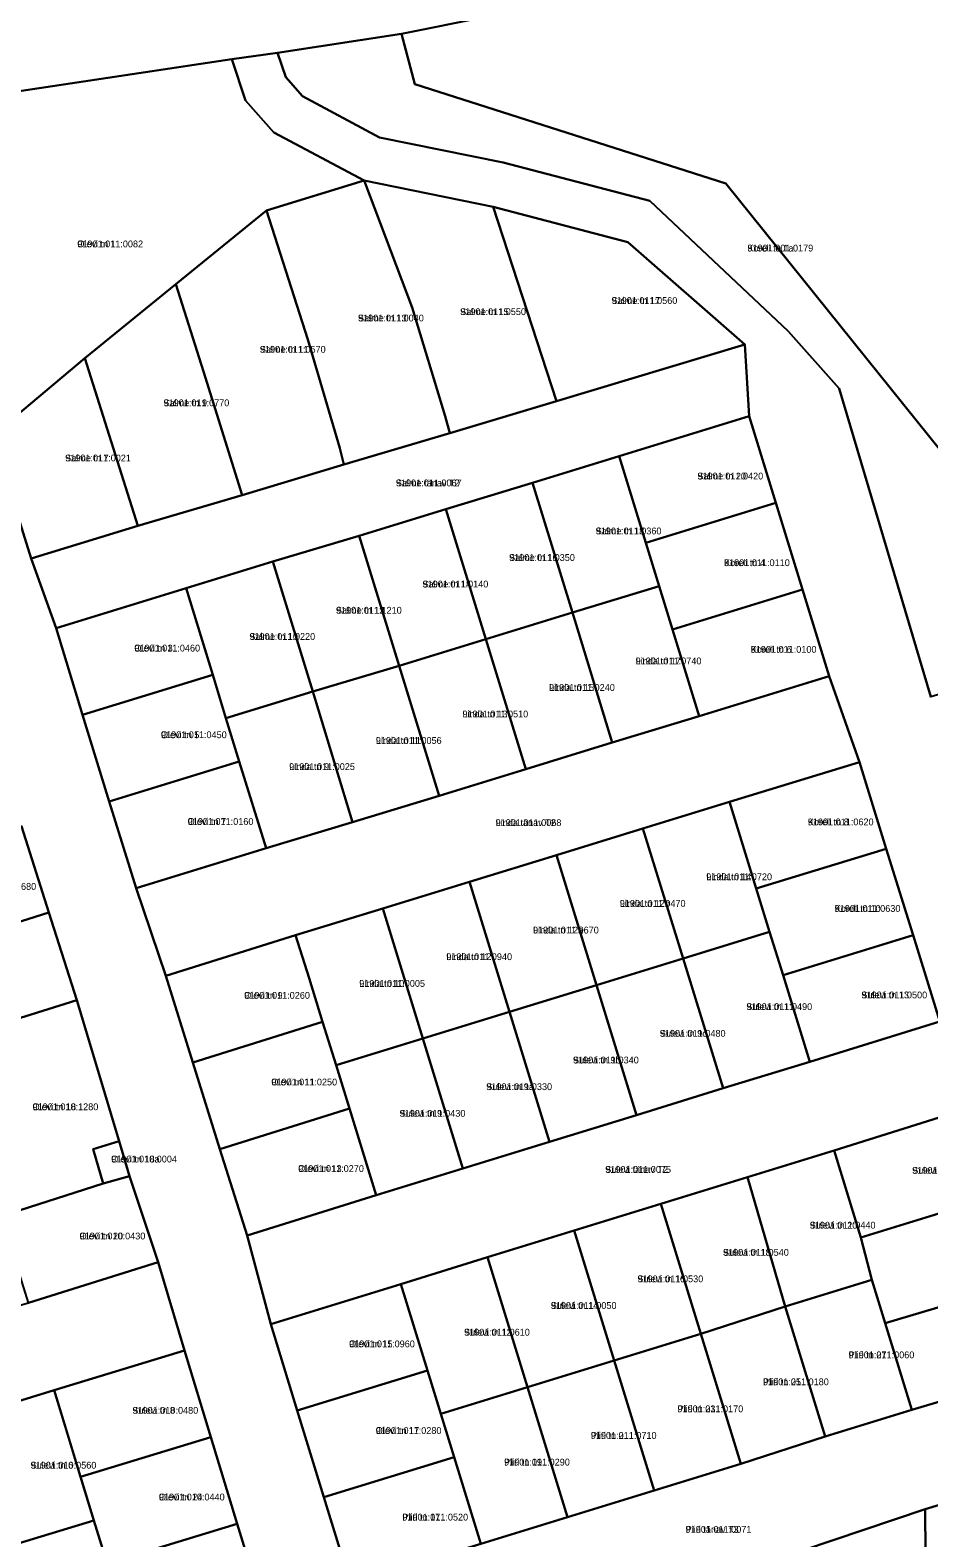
# Model space of a CAD drawing. Extents: x 675810 to 681273, y 6411190 to 6417565.
# Drawn here: x 678729.6 to 678927.8, y 6414897.2 to 6415229.9 of the extents above; entities that cross this region are included whole.
import ezdxf

# ---------------------------------------------------------------- set-up
doc = ezdxf.new("R2010")
doc.units = 0
for name, color, linetype in [('L_AADRESS', 7, 'Continuous'), ('PIIR', 7, 'Continuous'), ('TUNNUS', 7, 'Continuous')]:
    doc.layers.add(name, color=color, linetype=linetype)

msp = doc.modelspace()

# ---------------------------------------------------------------- linework, layer by layer
at = {"layer": 'PIIR'}
for points in [[(678938.21, 6415256.44), (678940.28, 6415250.38), (678947.08, 6415252.89), (678953.18, 6415237.02), (678971.88, 6415192.56), (678991.54, 6415146.92), (678991.43, 6415107.45), (678951.01, 6415123.4), (678930.74, 6415136.65), (678883.06, 6415196.06), (678814.45, 6415217.97), (678811.5, 6415229.05), (678924.62, 6415251.82)], [(678811.5, 6415229.05), (678814.45, 6415217.97), (678883.06, 6415196.06), (678930.74, 6415136.65), (678951.01, 6415123.4), (678991.43, 6415107.45), (678976.51, 6415097.38), (678928.23, 6415082.74), (678907.99, 6415150.83), (678896.81, 6415163.44), (678866.24, 6415192.19), (678833.97, 6415200.67), (678806.69, 6415206.19), (678789.69, 6415215.27), (678785.99, 6415219.46), (678784.18, 6415224.88)], [(678698.84, 6415212.11), (678774.11, 6415223.46), (678777.15, 6415214.36), (678783.39, 6415207.3), (678803.29, 6415196.66), (678781.73, 6415190.06), (678761.76, 6415173.8), (678741.72, 6415157.52), (678721.36, 6415140.44)], [(678822.16, 6415140.93), (678798.84, 6415134.04), (678797.92, 6415137.65), (678790.9, 6415161.63), (678781.73, 6415190.06), (678803.29, 6415196.66), (678813.86, 6415168.64), (678821.16, 6415144.73)], [(678821.16, 6415144.73), (678813.86, 6415168.64), (678803.29, 6415196.66), (678831.73, 6415190.9), (678845.66, 6415148.02), (678822.16, 6415140.93)], [(678861.44, 6415183.09), (678887.2, 6415160.51), (678845.66, 6415148.02), (678831.73, 6415190.9)], [(678781.73, 6415190.06), (678790.9, 6415161.63), (678797.92, 6415137.65), (678798.84, 6415134.04), (678776.38, 6415127.3), (678767.84, 6415154.55), (678761.76, 6415173.8)], [(678741.72, 6415157.52), (678761.76, 6415173.8), (678767.84, 6415154.55), (678776.38, 6415127.3), (678753.36, 6415120.49)], [(678721.36, 6415140.44), (678741.72, 6415157.52), (678753.36, 6415120.49), (678729.87, 6415113.29)], [(678729.87, 6415113.29), (678753.36, 6415120.49), (678776.38, 6415127.3), (678798.84, 6415134.04), (678822.16, 6415140.93), (678845.66, 6415148.02), (678887.2, 6415160.51), (678888.18, 6415144.69), (678859.5, 6415135.89), (678840.39, 6415130.02), (678821.32, 6415124.18), (678802.2, 6415118.31), (678783.14, 6415112.61), (678764.02, 6415106.74), (678735.34, 6415097.93)], [(678865.37, 6415116.77), (678859.5, 6415135.89), (678888.18, 6415144.69), (678894.05, 6415125.57)], [(678849.19, 6415101.34), (678840.39, 6415130.02), (678859.5, 6415135.89), (678865.37, 6415116.77), (678868.3, 6415107.21)], [(678821.32, 6415124.18), (678840.39, 6415130.02), (678849.19, 6415101.34), (678830.12, 6415095.5)], [(678871.24, 6415097.65), (678868.3, 6415107.21), (678865.37, 6415116.77), (678894.05, 6415125.57), (678899.92, 6415106.45)], [(678811, 6415089.63), (678802.2, 6415118.31), (678821.32, 6415124.18), (678830.12, 6415095.5)], [(678802.2, 6415118.31), (678811, 6415089.63), (678791.94, 6415083.93), (678783.14, 6415112.61)], [(678772.82, 6415078.06), (678769.89, 6415087.61), (678764.02, 6415106.74), (678783.14, 6415112.61), (678791.94, 6415083.93)], [(678741.21, 6415078.81), (678735.34, 6415097.93), (678764.02, 6415106.74), (678769.89, 6415087.61)], [(678858, 6415072.66), (678849.19, 6415101.34), (678868.3, 6415107.21), (678871.24, 6415097.65), (678877.12, 6415078.53)], [(678899.92, 6415106.45), (678905.79, 6415087.34), (678877.12, 6415078.53), (678871.24, 6415097.65)], [(678838.92, 6415066.83), (678830.12, 6415095.5), (678849.19, 6415101.34), (678858, 6415072.66)], [(678819.8, 6415060.95), (678811, 6415089.63), (678830.12, 6415095.5), (678838.92, 6415066.83)], [(678747.08, 6415059.69), (678741.21, 6415078.81), (678769.89, 6415087.61), (678772.82, 6415078.06), (678775.76, 6415068.49)], [(678791.94, 6415083.93), (678811, 6415089.63), (678819.8, 6415060.95), (678800.68, 6415055.08)], [(678753.01, 6415040.54), (678781.65, 6415049.38), (678800.68, 6415055.08), (678819.8, 6415060.95), (678838.92, 6415066.83), (678858, 6415072.66), (678877.12, 6415078.53), (678905.79, 6415087.34), (678912.53, 6415068.38), (678883.82, 6415059.57), (678864.76, 6415053.69), (678845.68, 6415047.81), (678826.55, 6415041.96), (678807.43, 6415036.08), (678788.16, 6415030.19), (678759.54, 6415021.18)], [(678772.82, 6415078.06), (678791.94, 6415083.93), (678800.68, 6415055.08), (678781.65, 6415049.38), (678775.76, 6415068.49)], [(678747.08, 6415059.69), (678775.76, 6415068.49), (678781.65, 6415049.38), (678753.01, 6415040.54)], [(678889.72, 6415040.46), (678883.82, 6415059.57), (678912.53, 6415068.38), (678918.4, 6415049.26)], [(678873.62, 6415025.05), (678864.76, 6415053.69), (678883.82, 6415059.57), (678889.72, 6415040.46), (678892.69, 6415030.93)], [(678699.15, 6415045.19), (678727.76, 6415054.23), (678733.78, 6415035.16), (678705.19, 6415026.12)], [(678845.68, 6415047.81), (678864.76, 6415053.69), (678873.62, 6415025.05), (678854.49, 6415019.16)], [(678845.68, 6415047.81), (678854.49, 6415019.16), (678835.37, 6415013.28), (678826.55, 6415041.96)], [(678924.33, 6415030.21), (678895.65, 6415021.37), (678892.69, 6415030.93), (678889.72, 6415040.46), (678918.4, 6415049.26)], [(678826.55, 6415041.96), (678835.37, 6415013.28), (678816.25, 6415007.4), (678807.43, 6415036.08)], [(678562.02, 6414983.35), (678608.15, 6414995.6), (678629.13, 6415002.22), (678648.2, 6415008.25), (678667, 6415014.19), (678686.1, 6415020.24), (678705.19, 6415026.12), (678733.78, 6415035.16), (678739.92, 6415015.81), (678711.08, 6415006.77), (678691.97, 6415000.89), (678672.85, 6414995.01), (678653.73, 6414989.12), (678634.61, 6414983.24), (678615.5, 6414977.36), (678611.82, 6414976.26), (678610.23, 6414981.4), (678604.57, 6414981.8), (678583.13, 6414976.97), (678565.58, 6414972.33)], [(678797.14, 6415001.52), (678794.11, 6415011.07), (678791.15, 6415020.66), (678788.16, 6415030.19), (678807.43, 6415036.08), (678816.25, 6415007.4)], [(678759.54, 6415021.18), (678788.16, 6415030.19), (678791.15, 6415020.66), (678794.11, 6415011.07), (678765.54, 6415002.11)], [(678882.46, 6414996.39), (678873.62, 6415025.05), (678892.69, 6415030.93), (678895.65, 6415021.37), (678901.53, 6415002.27)], [(678895.65, 6415021.37), (678924.33, 6415030.21), (678930.22, 6415011.1), (678901.53, 6415002.27)], [(678854.49, 6415019.16), (678873.62, 6415025.05), (678882.46, 6414996.39), (678863.31, 6414990.49)], [(678863.31, 6414990.49), (678844.19, 6414984.61), (678835.37, 6415013.28), (678854.49, 6415019.16)], [(678743.51, 6414983), (678745.76, 6414975.36), (678723.29, 6414968.17), (678719.9, 6414978.09), (678711.08, 6415006.77), (678739.92, 6415015.81), (678749.26, 6414984.72)], [(678777.48, 6414963.9), (678805.96, 6414972.84), (678825.07, 6414978.72), (678844.19, 6414984.61), (678863.31, 6414990.49), (678882.46, 6414996.39), (678901.53, 6415002.27), (678930.22, 6415011.1), (678935.25, 6414991.58), (678906.93, 6414982.64), (678887.82, 6414976.76), (678868.7, 6414970.88), (678849.58, 6414965), (678830.47, 6414959.11), (678811.35, 6414953.21), (678782.68, 6414944.38)], [(678835.37, 6415013.28), (678844.19, 6414984.61), (678825.07, 6414978.72), (678816.25, 6415007.4)], [(678765.54, 6415002.11), (678794.11, 6415011.07), (678797.14, 6415001.52), (678800.06, 6414991.96), (678771.49, 6414982.99)], [(678816.25, 6415007.4), (678825.07, 6414978.72), (678805.96, 6414972.84), (678800.06, 6414991.96), (678797.14, 6415001.52)], [(678771.49, 6414982.99), (678800.06, 6414991.96), (678805.96, 6414972.84), (678777.48, 6414963.9)], [(678906.93, 6414982.64), (678935.25, 6414991.58), (678941.44, 6414972.33), (678912.78, 6414963.51)], [(678751.51, 6414977.02), (678745.76, 6414975.36), (678743.51, 6414983), (678749.26, 6414984.72)], [(678896.13, 6414948.23), (678887.82, 6414976.76), (678906.93, 6414982.64), (678912.78, 6414963.51), (678915.25, 6414954.11)], [(678723.29, 6414968.17), (678745.76, 6414975.36), (678751.51, 6414977.02), (678757.87, 6414958), (678729.28, 6414949.08)], [(678887.82, 6414976.76), (678896.13, 6414948.23), (678877.52, 6414942.2), (678868.7, 6414970.88)], [(678918.19, 6414944.55), (678915.25, 6414954.11), (678912.78, 6414963.51), (678941.44, 6414972.33), (678947.33, 6414953.22)], [(678868.7, 6414970.88), (678877.52, 6414942.2), (678858.4, 6414936.32), (678849.58, 6414965)], [(678839.29, 6414930.44), (678830.47, 6414959.11), (678849.58, 6414965), (678858.4, 6414936.32)], [(678633.14, 6414920.01), (678652.26, 6414925.89), (678671.37, 6414931.77), (678690.49, 6414937.66), (678709.66, 6414943.54), (678729.28, 6414949.08), (678757.87, 6414958), (678763.64, 6414938.53), (678734.94, 6414929.77), (678715.79, 6414923.89), (678696.65, 6414918.05), (678677.15, 6414912.15), (678657.96, 6414906.51), (678638.95, 6414900.92)], [(678830.47, 6414959.11), (678839.29, 6414930.44), (678820.17, 6414924.56), (678817.24, 6414934.11), (678811.35, 6414953.21)], [(678782.68, 6414944.38), (678811.35, 6414953.21), (678817.24, 6414934.11), (678788.55, 6414925.29)], [(678904.95, 6414919.55), (678896.13, 6414948.23), (678915.25, 6414954.11), (678918.19, 6414944.55), (678924.07, 6414925.43)], [(678918.19, 6414944.55), (678947.33, 6414953.22), (678953.22, 6414934.12), (678924.07, 6414925.43)], [(678886.34, 6414913.53), (678877.52, 6414942.2), (678896.13, 6414948.23), (678904.95, 6414919.55)], [(678877.52, 6414942.2), (678886.34, 6414913.53), (678867.23, 6414907.65), (678858.4, 6414936.32)], [(678737.86, 6414920.17), (678734.94, 6414929.77), (678763.64, 6414938.53), (678769.47, 6414919.4), (678740.77, 6414910.65)], [(678858.4, 6414936.32), (678867.23, 6414907.65), (678848.11, 6414901.76), (678839.29, 6414930.44)], [(678820.17, 6414924.56), (678823.1, 6414914.99), (678794.43, 6414906.16), (678788.55, 6414925.29), (678817.24, 6414934.11)], [(678800.31, 6414887.05), (678828.99, 6414895.88), (678848.11, 6414901.76), (678867.23, 6414907.65), (678886.34, 6414913.53), (678904.95, 6414919.55), (678924.07, 6414925.43), (678953.22, 6414934.12), (678953.21, 6414911.44), (678926.95, 6414903.55), (678879.9, 6414887.67), (678849.35, 6414877.97), (678801.1, 6414862.51)], [(678734.94, 6414929.77), (678740.77, 6414910.65), (678740.89, 6414910.26), (678743.69, 6414901.05), (678724.56, 6414895.21), (678715.79, 6414923.89)], [(678839.29, 6414930.44), (678848.11, 6414901.76), (678828.99, 6414895.88), (678823.1, 6414914.99), (678820.17, 6414924.56)], [(678743.69, 6414901.05), (678740.77, 6414910.65), (678769.47, 6414919.4), (678775.3, 6414900.27), (678746.6, 6414891.52)], [(678794.43, 6414906.16), (678823.1, 6414914.99), (678828.99, 6414895.88), (678800.31, 6414887.05)], [(678956.03, 6414872.89), (678927.3, 6414864.25), (678926.95, 6414903.55), (678953.21, 6414911.44)], [(678890.46, 6414861.39), (678888.36, 6414860.74), (678879.9, 6414887.67), (678926.95, 6414903.55), (678927.3, 6414864.25), (678902.08, 6414856.43)], [(678743.69, 6414901.05), (678746.6, 6414891.52), (678752.51, 6414872.36), (678733.39, 6414866.53), (678724.56, 6414895.21)], [(678781.19, 6414881.15), (678752.51, 6414872.36), (678746.6, 6414891.52), (678775.3, 6414900.27)]]:
    msp.add_lwpolyline(points, close=True, dxfattribs=at)
for points in [[(678924.62, 6415251.82), (678811.5, 6415229.05), (678784.18, 6415224.88), (678774.11, 6415223.46), (678698.84, 6415212.11), (678679.92, 6415209.28), (678638.48, 6415203.25), (678618.83, 6415200.88), (678611.3, 6415200.13), (678589.01, 6415197.59), (678588.32, 6415200.94), (678565.47, 6415198.06), (678556.75, 6415193.84), (678515.07, 6415188.65), (678505.53, 6415212.72), (678525.66, 6415216.01), (678582.57, 6415225.11), (678581.03, 6415234.94)], [(678930.22, 6415011.1), (678924.33, 6415030.21), (678918.4, 6415049.26), (678912.53, 6415068.38), (678905.79, 6415087.34), (678899.92, 6415106.45), (678894.05, 6415125.57), (678888.18, 6415144.69), (678887.2, 6415160.51), (678861.44, 6415183.09), (678831.73, 6415190.9), (678803.29, 6415196.66), (678783.39, 6415207.3), (678777.15, 6415214.36), (678774.11, 6415223.46), (678784.18, 6415224.88), (678785.99, 6415219.46), (678789.69, 6415215.27), (678806.69, 6415206.19), (678833.97, 6415200.67), (678866.24, 6415192.19), (678896.81, 6415163.44), (678907.99, 6415150.83), (678928.23, 6415082.74)], [(678721.36, 6415140.44), (678729.87, 6415113.29), (678735.34, 6415097.93), (678741.21, 6415078.81), (678747.08, 6415059.69), (678753.01, 6415040.54), (678759.54, 6415021.18), (678765.54, 6415002.11), (678771.49, 6414982.99), (678777.48, 6414963.9), (678782.68, 6414944.38), (678788.55, 6414925.29), (678794.43, 6414906.16), (678800.31, 6414887.05)], [(678781.19, 6414881.15), (678775.3, 6414900.27), (678769.47, 6414919.4), (678763.64, 6414938.53), (678757.87, 6414958), (678751.51, 6414977.02), (678749.26, 6414984.72), (678739.92, 6415015.81), (678733.78, 6415035.16), (678727.76, 6415054.23)]]:
    msp.add_lwpolyline(points, dxfattribs=at)

# ---------------------------------------------------------------- texts
at = {"layer": 'L_AADRESS'}
for s, p in [('Olevi tn 1', (678740.04, 6415181.95)), ('Koreli tn 1a', (678887.8, 6415181.03)), ('Salme tn 17', (678857.84, 6415169.46)), ('Salme tn 15', (678824.47, 6415167)), ('Salme tn 13', (678801.94, 6415165.6)), ('Salme tn 11', (678780.3, 6415158.69)), ('Salme tn 9', (678759.05, 6415146.89)), ('Salme tn 7', (678737.36, 6415134.72)), ('Salme tn 20', (678876.77, 6415130.73)), ('Salme tänav T2', (678810.28, 6415129.22)), ('Salme tn 18', (678854.34, 6415118.62)), ('Salme tn 16', (678835.25, 6415112.76)), ('Koreli tn 4', (678882.64, 6415111.61)), ('Salme tn 14', (678816.16, 6415106.9)), ('Salme tn 12', (678797.07, 6415101.12)), ('Olevi tn 3', (678752.61, 6415092.77)), ('Salme tn 10', (678777.98, 6415095.33)), ('Linda tn 17', (678863.15, 6415089.94)), ('Koreli tn 6', (678888.52, 6415092.49)), ('Linda tn 15', (678844.06, 6415084.08)), ('Linda tn 13', (678824.96, 6415078.23)), ('Olevi tn 5', (678758.48, 6415073.65)), ('Linda tn 11', (678805.87, 6415072.38)), ('Linda tn 9', (678786.75, 6415066.62)), ('Olevi tn 7', (678764.37, 6415054.51)), ('Linda tänav T2', (678832.28, 6415054.26)), ('Koreli tn 8', (678901.11, 6415054.42)), ('Linda tn 14', (678878.72, 6415042.31)), ('Linda tn 12b', (678859.65, 6415036.43)), ('Koreli tn 10', (678907.03, 6415035.32)), ('Linda tn 12a', (678840.52, 6415030.55)), ('Linda tn 12', (678821.4, 6415024.68)), ('Linda tn 10', (678802.2, 6415018.78)), ('Sulevi tn 13', (678912.93, 6415016.24)), ('Olevi tn 9', (678776.83, 6415016.15)), ('Sulevi tn 11', (678887.57, 6415013.66)), ('Sulevi tn 9c', (678868.48, 6415007.77)), ('Sulevi tn 9b', (678849.34, 6415001.88)), ('Olevi tn 11', (678782.82, 6414997.03)), ('Sulevi tn 9a', (678830.22, 6414996)), ('Olevi tn 18', (678730.17, 6414991.56)), ('Sulevi tn 9', (678811.11, 6414990.12)), ('Olevi tn 18a', (678747.51, 6414980.03)), ('Olevi tn 13', (678788.73, 6414977.93)), ('Sulevi tänav T2', (678856.45, 6414977.74)), ('Sulevi tn 22', (678924.13, 6414977.54)), ('Olevi tn 20', (678740.54, 6414963.05)), ('Sulevi tn 20', (678901.54, 6414965.44)), ('Sulevi tn 18', (678882.42, 6414959.44)), ('Sulevi tn 16', (678863.55, 6414953.6)), ('Sulevi tn 14', (678844.43, 6414947.72)), ('Sulevi tn 12', (678825.32, 6414941.83)), ('Olevi tn 15', (678799.96, 6414939.25)), ('Piiri tn 27', (678910.1, 6414936.83)), ('Piiri tn 25', (678891.24, 6414930.88)), ('Sulevi tn 8', (678752.2, 6414924.59)), ('Piiri tn 23', (678872.37, 6414924.92)), ('Olevi tn 17', (678805.83, 6414920.13)), ('Piiri tn 21', (678853.26, 6414919.04)), ('Piiri tn 19', (678834.14, 6414913.16)), ('Sulevi tn 6', (678729.74, 6414912.48)), ('Olevi tn 24', (678758.03, 6414905.46)), ('Piiri tn 17', (678811.71, 6414901.02)), ('Piiri tänav T3', (678874.17, 6414898.32))]:
    msp.add_text(s, height=1.5, dxfattribs=at).set_placement(p)
at = {"layer": 'TUNNUS'}
for s, p in [('91901:011:0082', (678740.04, 6415181.95)), ('91901:001:0179', (678887.8, 6415181.03)), ('91901:011:0560', (678857.84, 6415169.46)), ('91901:011:0550', (678824.47, 6415167)), ('91901:011:0040', (678801.94, 6415165.6)), ('91901:011:0570', (678780.3, 6415158.69)), ('91901:011:0770', (678759.05, 6415146.89)), ('91901:011:0021', (678737.36, 6415134.72)), ('91901:011:0420', (678876.77, 6415130.73)), ('91901:011:0067', (678810.28, 6415129.22)), ('91901:011:0360', (678854.34, 6415118.62)), ('91901:011:0350', (678835.25, 6415112.76)), ('91901:011:0110', (678882.64, 6415111.61)), ('91901:011:0140', (678816.16, 6415106.9)), ('91901:011:1210', (678797.07, 6415101.12)), ('91901:011:0460', (678752.61, 6415092.77)), ('91901:011:0220', (678777.98, 6415095.33)), ('91901:011:0740', (678863.15, 6415089.94)), ('91901:011:0100', (678888.52, 6415092.49)), ('91901:011:0240', (678844.06, 6415084.08)), ('91901:011:0510', (678824.96, 6415078.23)), ('91901:011:0450', (678758.48, 6415073.65)), ('91901:011:0056', (678805.87, 6415072.38)), ('91901:011:0025', (678786.75, 6415066.62)), ('91901:011:0160', (678764.37, 6415054.51)), ('91901:011:0068', (678832.28, 6415054.26)), ('91901:011:0620', (678901.11, 6415054.42)), ('91901:010:0680', (678716.47, 6415040.18)), ('91901:011:0720', (678878.72, 6415042.31)), ('91901:011:0470', (678859.65, 6415036.43)), ('91901:011:0630', (678907.03, 6415035.32)), ('91901:011:0670', (678840.52, 6415030.55)), ('91901:011:0940', (678821.4, 6415024.68)), ('91901:011:0005', (678802.2, 6415018.78)), ('91901:011:0500', (678912.93, 6415016.24)), ('91901:011:0260', (678776.83, 6415016.15)), ('91901:011:0490', (678887.57, 6415013.66)), ('91901:011:0480', (678868.48, 6415007.77)), ('91901:011:0340', (678849.34, 6415001.88)), ('91901:011:0250', (678782.82, 6414997.03)), ('91901:011:0330', (678830.22, 6414996)), ('91901:010:1280', (678730.17, 6414991.56)), ('91901:011:0430', (678811.11, 6414990.12)), ('91901:010:0004', (678747.51, 6414980.03)), ('91901:011:0270', (678788.73, 6414977.93)), ('91901:011:0075', (678856.45, 6414977.74)), ('91901:011:0018', (678924.13, 6414977.54)), ('91901:010:0430', (678740.54, 6414963.05)), ('91901:011:0440', (678901.54, 6414965.44)), ('91901:011:0540', (678882.42, 6414959.44)), ('91901:011:0530', (678863.55, 6414953.6)), ('91901:011:0050', (678844.43, 6414947.72)), ('91901:011:0610', (678825.32, 6414941.83)), ('91901:011:0960', (678799.96, 6414939.25)), ('91901:011:0060', (678910.1, 6414936.83)), ('91901:011:0180', (678891.24, 6414930.88)), ('91901:010:0480', (678752.2, 6414924.59)), ('91901:011:0170', (678872.37, 6414924.92)), ('91901:011:0280', (678805.83, 6414920.13)), ('91901:011:0710', (678853.26, 6414919.04)), ('91901:011:0290', (678834.14, 6414913.16)), ('91901:010:0560', (678729.74, 6414912.48)), ('91901:010:0440', (678758.03, 6414905.46)), ('91901:011:0520', (678811.71, 6414901.02)), ('91901:011:0071', (678874.17, 6414898.32))]:
    msp.add_text(s, height=1.5, dxfattribs=at).set_placement(p)

doc.saveas('drawing.dxf')
